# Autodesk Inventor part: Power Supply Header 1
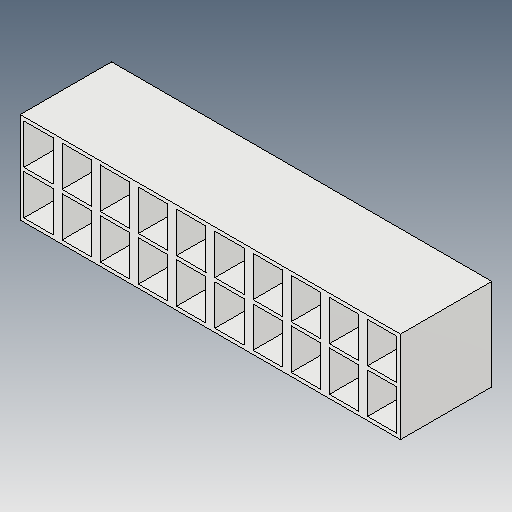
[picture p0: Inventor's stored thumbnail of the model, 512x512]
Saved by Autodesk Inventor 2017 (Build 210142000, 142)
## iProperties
Created: 2005-12
Part Number: Power Supply Header 1
Material: Generic
Document SubType Name: Modeling
Designer: DanielSeverino
Density: 1 g/cm^3
Appearance: Default
Author: DanielSeverino
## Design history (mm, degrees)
feature "Solid1"
body "Solid2"
